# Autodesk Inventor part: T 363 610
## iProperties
Company: Mayer & Müller AG Schaltgeräte
Created: 2006-09
Part Number: T 363 610
Material: 1.0330.03
Document SubType Name: Sheet Metal
Designer: I.Baliuc
Description: Winkel
Density: 7.84 g/cm^3
Sheet Metal Rule: Default
Mass: 87.3919 g
Surface Area: 84.1338 cm^2
Volume: 11.1469 cm^3
Zweck: für HiKo / Vorkontakt
Abmessung: St.Bl. 3 mm
Author: T.Messerschmitt
Keywords: 266493
Revision Number: 363610
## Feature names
1. Bohrung_Ø5.2 [Hole]
2. Bohrung_M4_01 [Hole]
3. Bohrung_M4_02 [Hole]
4. Grobblech1
5. Grobblech2
6. Biegung1
